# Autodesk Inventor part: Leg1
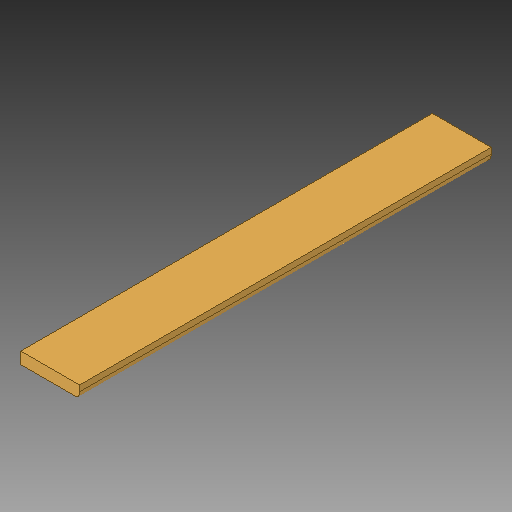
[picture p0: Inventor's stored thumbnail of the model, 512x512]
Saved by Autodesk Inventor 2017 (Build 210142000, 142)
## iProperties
Created: 2017-05
Part Number: Leg1
Material: Generic
Document SubType Name: Modeling
Designer: Savy
Density: 1 g/cm^3
Appearance: Default
Author: Savy
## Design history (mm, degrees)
feature "Base1"
body "Solid1"
